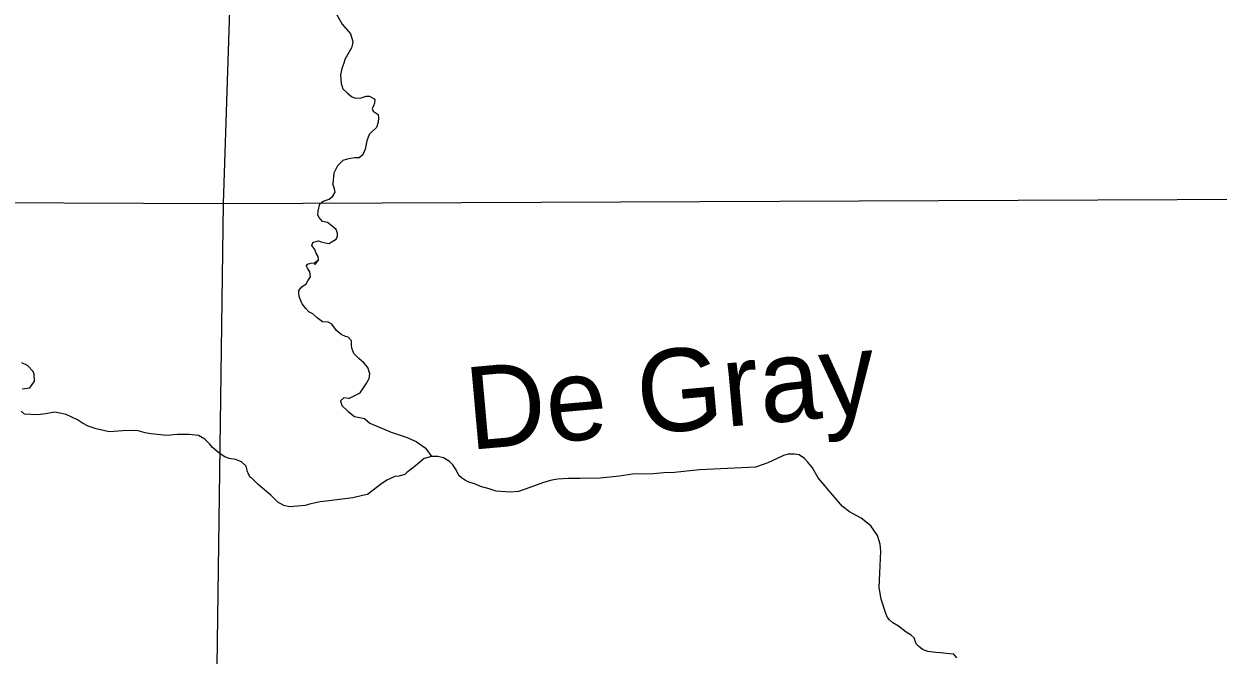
# Model space of a CAD drawing. Extents: x 1373862 to 1377080, y 1164775 to 1170415.
# Drawn here: x 1375269.5 to 1375368.7, y 1168662.2 to 1168714.6 of the extents above; entities that cross this region are included whole.
import ezdxf

# ---------------------------------------------------------------- set-up
doc = ezdxf.new("R2010")
doc.units = 0
doc.layers.add('Level 35', color=7, linetype='Continuous')
doc.layers.add('Level 5', color=7, linetype='Continuous')

msp = doc.modelspace()

# ---------------------------------------------------------------- linework, layer by layer
at = {"layer": 'Level 35'}
for points in [[(1375291.351, 1168716.848), (1375291.772, 1168716.58), (1375291.941, 1168716.2), (1375292.3, 1168715.967), (1375292.596, 1168715.777), (1375293.04, 1168715.925), (1375293.378, 1168716.157), (1375293.779, 1168716.39), (1375294.223, 1168716.411), (1375294.624, 1168716.326), (1375295.195, 1168715.925), (1375295.511, 1168715.333), (1375295.955, 1168714.571), (1375296.652, 1168713.768), (1375296.842, 1168713.112), (1375296.8, 1168712.943), (1375296.716, 1168712.584), (1375296.166, 1168711.632), (1375296.082, 1168711.336), (1375295.934, 1168710.871), (1375295.807, 1168710.342)], [(1375295.807, 1168710.342), (1375295.871, 1168709.63), (1375296.018, 1168709.186), (1375296.357, 1168708.869), (1375296.716, 1168708.551), (1375297.033, 1168708.425), (1375297.518, 1168708.446), (1375297.941, 1168708.594), (1375298.216, 1168708.594), (1375298.617, 1168708.361), (1375298.659, 1168708.277), (1375298.638, 1168708.002), (1375298.554, 1168707.769), (1375298.448, 1168707.536), (1375298.533, 1168707.325), (1375298.955, 1168707.05), (1375298.976, 1168706.796), (1375298.955, 1168706.416), (1375298.807, 1168705.972), (1375298.406, 1168705.612), (1375298.195, 1168705.401), (1375298.004, 1168704.872), (1375297.857, 1168704.174), (1375297.666, 1168703.709), (1375297.371, 1168703.477), (1375296.969, 1168703.456), (1375296.378, 1168703.35), (1375296.018, 1168703.244), (1375295.575, 1168702.8), (1375295.258, 1168702.187), (1375295.173, 1168701.299)], [(1375294.732, 1168698.093), (1375294.307, 1168698.18), (1375294.054, 1168698.497), (1375293.927, 1168698.708), (1375293.948, 1168699.026), (1375294.096, 1168699.641), (1375294.371, 1168699.852), (1375294.878, 1168700.041), (1375295.173, 1168700.273), (1375295.364, 1168700.611), (1375295.321, 1168700.886), (1375295.173, 1168701.299)], [(1375293.695, 1168694.564), (1375293.99, 1168694.987), (1375293.969, 1168695.262), (1375293.758, 1168695.6), (1375293.673, 1168695.854), (1375293.441, 1168696.192), (1375293.504, 1168696.446), (1375293.864, 1168696.552), (1375293.99, 1168696.573), (1375294.202, 1168696.488), (1375294.666, 1168696.383), (1375294.878, 1168696.361), (1375295.11, 1168696.509), (1375295.448, 1168696.721), (1375295.575, 1168696.953), (1375295.575, 1168697.186), (1375295.448, 1168697.503), (1375295.131, 1168697.799), (1375294.835, 1168698.011), (1375294.732, 1168698.093)], [(1375296.757, 1168687.67), (1375296.737, 1168687.933), (1375296.737, 1168688.271), (1375296.441, 1168688.567), (1375296.23, 1168688.631), (1375295.871, 1168688.8), (1375295.469, 1168689.138), (1375295.089, 1168689.646), (1375294.793, 1168689.815), (1375294.328, 1168689.836), (1375293.864, 1168690.174), (1375293.504, 1168690.513), (1375293.187, 1168690.682), (1375292.934, 1168690.957), (1375292.638, 1168691.337), (1375292.406, 1168691.866), (1375292.342, 1168692.183), (1375292.364, 1168692.437), (1375292.596, 1168692.754), (1375292.955, 1168693.008), (1375293.103, 1168693.24), (1375293.314, 1168693.579), (1375293.272, 1168694.002), (1375293.061, 1168694.298), (1375293.018, 1168694.403), (1375292.997, 1168694.488), (1375293.061, 1168694.636), (1375293.356, 1168694.72), (1375293.652, 1168694.742), (1375293.99, 1168694.987)], [(1375296.504, 1168683.486), (1375297.451, 1168683.951), (1375297.937, 1168684.691), (1375298.19, 1168685.135), (1375298.254, 1168685.516), (1375298.085, 1168686.045), (1375297.789, 1168686.425), (1375297.345, 1168686.806), (1375296.923, 1168687.208), (1375296.757, 1168687.67)], [(1375269.362, 1168684.29), (1375269.996, 1168684.354), (1375270.397, 1168684.925), (1375270.355, 1168685.496), (1375270.271, 1168685.728), (1375269.806, 1168686.215), (1375269.341, 1168686.426)], [(1375296.504, 1168683.486), (1375296.082, 1168683.528), (1375295.807, 1168683.296), (1375295.934, 1168682.894), (1375296.441, 1168682.387), (1375296.99, 1168681.985), (1375297.814, 1168681.816), (1375298.258, 1168681.435), (1375300.033, 1168680.674), (1375301.279, 1168680.272), (1375302.103, 1168679.913), (1375302.842, 1168679.384), (1375303.138, 1168679.025), (1375303.383, 1168678.672)], [(1375325.642, 1168677.551), (1375323.572, 1168677.34), (1375322.684, 1168677.319), (1375321.797, 1168677.213), (1375320.086, 1168677.192), (1375318.987, 1168677.023), (1375317.381, 1168676.875), (1375315.738, 1168676.832), (1375314.766, 1168676.832), (1375313.879, 1168676.79), (1375313.371, 1168676.684), (1375312.674, 1168676.515), (1375311.639, 1168676.114), (1375310.604, 1168675.754), (1375309.907, 1168675.712), (1375308.745, 1168675.796), (1375308.157, 1168675.966), (1375307.439, 1168676.177), (1375307.038, 1168676.367), (1375306.467, 1168676.536), (1375306.193, 1168676.663), (1375305.855, 1168676.896), (1375305.643, 1168677.086), (1375305.411, 1168677.551), (1375305.136, 1168677.974), (1375304.862, 1168678.249), (1375304.376, 1168678.545), (1375303.89, 1168678.672), (1375303.383, 1168678.672), (1375302.77, 1168678.482), (1375302.052, 1168677.89), (1375301.333, 1168677.34), (1375301.164, 1168677.171), (1375300.678, 1168677.023), (1375300.34, 1168677.002), (1375299.664, 1168676.684), (1375299.136, 1168676.325), (1375298.524, 1168675.86), (1375298.059, 1168675.5), (1375297.636, 1168675.416), (1375296.833, 1168675.225), (1375294.636, 1168674.951), (1375294.133, 1168674.887), (1375293.246, 1168674.697), (1375292.866, 1168674.591), (1375292.232, 1168674.528), (1375291.577, 1168674.485), (1375291.112, 1168674.591), (1375290.605, 1168674.866), (1375290.014, 1168675.458), (1375289, 1168676.304), (1375288.412, 1168676.896), (1375288.307, 1168676.959), (1375288.18, 1168677.192), (1375288.095, 1168677.425), (1375287.969, 1168677.848), (1375287.588, 1168678.228), (1375287.102, 1168678.418), (1375286.553, 1168678.503), (1375286.215, 1168678.63), (1375285.729, 1168678.947), (1375285.18, 1168679.412), (1375284.926, 1168679.708), (1375284.546, 1168680.11), (1375284.018, 1168680.406), (1375283.236, 1168680.491), (1375282.285, 1168680.491), (1375281.377, 1168680.406), (1375280.067, 1168680.533), (1375279.581, 1168680.617), (1375279.011, 1168680.787), (1375278.44, 1168680.808), (1375277.722, 1168680.787), (1375276.602, 1168680.723), (1375275.525, 1168680.956), (1375274.849, 1168681.167), (1375274.369, 1168681.421), (1375273.968, 1168681.696), (1375273.017, 1168682.14), (1375272.51, 1168682.267), (1375272.045, 1168682.33), (1375271.327, 1168682.203), (1375270.609, 1168682.119), (1375269.552, 1168682.182), (1375269.278, 1168682.436)], [(1375333.011, 1168678.868), (1375332.614, 1168678.735), (1375332.086, 1168678.482), (1375331.325, 1168678.143), (1375330.29, 1168677.784), (1375327.966, 1168677.678), (1375325.642, 1168677.551)], [(1375343.629, 1168663.113), (1375343.486, 1168663.591), (1375343.232, 1168663.824), (1375342.81, 1168664.078), (1375342.176, 1168664.564), (1375341.69, 1168664.86), (1375341.436, 1168665.093), (1375341.267, 1168665.283), (1375341.12, 1168665.621), (1375340.718, 1168666.826), (1375340.57, 1168667.778), (1375340.634, 1168668.962), (1375340.697, 1168670.802), (1375340.655, 1168671.373), (1375340.422, 1168672.113), (1375339.873, 1168672.916), (1375339.07, 1168673.551), (1375338.098, 1168674.069), (1375337.507, 1168674.513), (1375336.725, 1168675.443), (1375335.5, 1168676.902), (1375335.018, 1168677.727), (1375334.638, 1168678.192), (1375334.363, 1168678.509), (1375333.919, 1168678.805), (1375333.539, 1168678.868), (1375333.011, 1168678.868)], [(1375347.031, 1168661.929), (1375346.756, 1168662.247), (1375346.418, 1168662.268), (1375345.658, 1168662.352), (1375345.277, 1168662.395), (1375344.601, 1168662.479), (1375344.158, 1168662.648), (1375343.82, 1168662.923), (1375343.629, 1168663.113)]]:
    msp.add_lwpolyline(points, dxfattribs=at)
at = {"layer": 'Level 5'}
for points in [[(1375287.27, 1168736.018), (1375286.079, 1168699.66)], [(1375233.025, 1168699.888), (1375286.079, 1168699.66)], [(1375286.079, 1168699.66), (1375284.891, 1168614.719)], [(1375286.079, 1168699.66), (1375371.946, 1168700.031)]]:
    msp.add_lwpolyline(points, dxfattribs=at)

# ---------------------------------------------------------------- texts
at = {"layer": 'Level 35'}
msp.add_text('De Gray', height=6.8431, rotation=5.14782, dxfattribs=at).set_placement((1375306.546, 1168679.203))

doc.saveas('drawing.dxf')
